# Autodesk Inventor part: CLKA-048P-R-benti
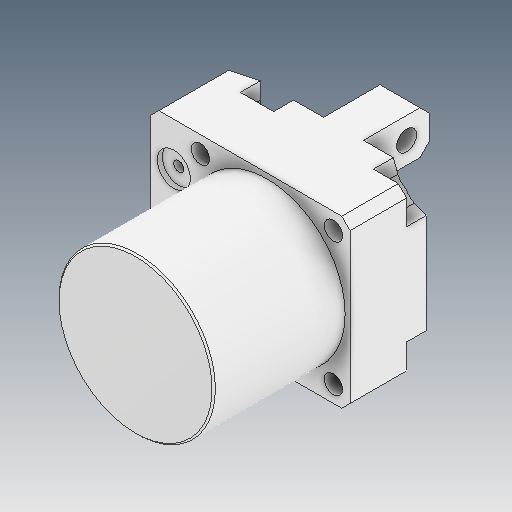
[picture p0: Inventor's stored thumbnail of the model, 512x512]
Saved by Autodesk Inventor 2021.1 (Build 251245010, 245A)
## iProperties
Created: 2021-06
Part Number: CLKA-048P-R-benti
Material: Ogólny
Document SubType Name: Modeling
Designer: user
Density: 1 g/cm^3
Appearance: Domyślna
Author: user
Revision Number: ÈÎºÎ
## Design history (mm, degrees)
feature "ÇÐ³ý-Ðý×ª6"
node "Bryła1"
